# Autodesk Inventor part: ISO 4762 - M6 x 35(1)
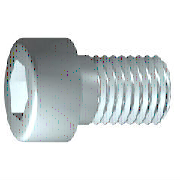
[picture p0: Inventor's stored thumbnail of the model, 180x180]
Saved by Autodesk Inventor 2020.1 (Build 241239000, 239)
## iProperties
Created: 2019-01
Part Number: ISO 4762 - M6 x 35(1)
Material: Edelstahl, 440C
Description: Innensechskantschraube
Document SubType Name: Modeling
Standard: ISO 4762
Designer: lutzd
Standard Revision: Fourth edition 2004-03-01
Standards Organization: ISO
Language: de-DE
Size Designation: M6 x 35
Categories: <MemberInstance><Categories><Category DisplayName="Verbindungselemente" InternalName="e4da775c-781d-43d5-af7c-5136215cf5a6" Mnemonic="FSTN"><Category DisplayNam
Mass: 10.6649 g
Surface Area: 10.4684 cm^2
Volume: 1.37612 cm^3
Density: 7.75 g/cm^3
Appearance: Halbpoliert
IsCustomPart: 0
Author: lutzd
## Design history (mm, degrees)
body "Solid1"
sketch "Skizze1"
  geometry: L1 (-1.333, 0)-(35, 0); L2 (35, 0)-(35, 3); L3 (35, 3)-(11, 3); L4 (11, 3)-(10.386, 3); L5 (10.386, 3)-(0, 3); L6 (0, 3)-(0, 5); L7 (0, 5)-(-6, 5); L8 (-6, 5)-(-6, 2.887); L9 (-6, 2.887)-(-3, 2.887); L10 (-3, 2.887)-(-1.333, 0); L11 (-14.2, 0)-(43.2, 0) reference; L12 (0, -1)-(0, 6) reference; L13 (11, 3)-(0, 3)
  constraints: 22 end point, 6 parallel, 2 collinear, 2 perpendicular, 1 horizontal, 1 point on line
  dimensions: "d1" = 24 distance from line of L3.end L2 (= GEL); "d2" = 0.61355 distance of L4.end L3.end (computed from GAL); "d3" = 6 distance between parallel lines of L8 L6 (= KOH); "d4" = 3 distance of L8.end L9.end (= INTI); "d5" = 60 deg angle of L10 L1; "d6" = 6 diameter of L3 L1 (= GD); "d7" = 6 diameter of L5 L1 (= BDM); "d8" = 5.7735 diameter of L9 L1 (= 1.1547 x SW); "d9" = 10 diameter of L7 L1 (= KOD); "d26" = 35 distance between parallel lines of L12 L2 (= NLG)
workplane "Work Plane1"
fillet "Fillet2" dims "d30" = 0.1 (= R)
revolve "Körper" stored, may be unused: angle "d10" = 90 deg
sketch "Skizze2"
  geometry: L1 (0, -7)-(0, 7) reference; L2 (-7, 0)-(7, 0) reference; L3 (2.887, 0)-(1.443, -2.5); L4 (1.443, -2.5)-(-1.443, -2.5); L5 (-1.443, -2.5)-(-2.887, 0); L6 (-2.887, 0)-(-1.443, 2.5); L7 (-1.443, 2.5)-(1.443, 2.5); L8 (1.443, 2.5)-(2.887, 0); 2 further points
  constraints: 12 end point, 1 coincident, 1 horizontal alignment, 1 point on line, 12 other
extrude "Loch" join sketch "Skizze2" stored distance "d11" = 10; taper "d12" = 0 deg
fillet "Rundung1" dims "d17" = 0.6 (= RR)
feature "Gewinde" dims "d13" = 24 (= GEL), "d14" = 0
chamfer "Fase1" distance "d15" = 0.61345 (= -0.5 x SPD + 0.5 x GD); stored, may be unused: second distance "d16" = 0.61345 (= GUL), angle "d27" = 45 deg
other parameters: "GD" = 6 [user parameter; used in 2 equation terms], "NLG" = 35 [user parameter; used in 1 equation term], "GEL" = 24 [user parameter; used in 2 equation terms], "KOD" = 10 [user parameter; used in 1 equation term], "KOH" = 6 [user parameter; used in 1 equation term], "INTI" = 3 [user parameter; used in 1 equation term], "GAL" = 0.61345 (= 0.61345 x PTC) [user parameter; used in 1 equation term], "GUL" = 0.61345 (= 0.61345 x PTC) [user parameter; used in 1 equation term], "BDM" = 6 (= NND) [user parameter; used in 1 equation term], "SW" = 5 [user parameter; used in 2 equation terms], "RR" = 0.6 [user parameter; used in 1 equation term], "SPD" = 4.7731 (= NND - 1.2269 x PTC) [user parameter; used in 1 equation term], "d19" = 0, "d28" = 0, "d29" = 0, "R" = 0.1 [user parameter; used in 1 equation term], "TOA" = 30 deg [user parameter], "GD1" = 4.7731 (= THREADDIA - 1.2269 x PTC) [user parameter], "THREADDIA" = 6 [user parameter; used in 1 equation term], "FAWI" = 45 deg [user parameter], "PTC" = 1 [user parameter; used in 5 equation terms], "NND" = 6 [user parameter; used in 2 equation terms], "E0" = 5.775 (= 1.155 x SW) [user parameter]
